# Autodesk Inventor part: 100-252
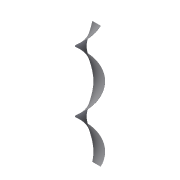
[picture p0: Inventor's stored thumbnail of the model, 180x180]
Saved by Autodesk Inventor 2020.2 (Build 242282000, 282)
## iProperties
Created: 2011-01
Part Number: 100-252
Document SubType Name: Modeling
Designer: F.Stasiak
Density: 1 g/cm^3
Material: Ogólny
Appearance: Domyślna
Company: Fabian Stasiak CAD Consulting
Manager: www.cadconsulting.pl
Author: F.Stasiak
Subject: Zbiór ćwiczeń. Autodesk Inventor 2020. Kurs podstawowy
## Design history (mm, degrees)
sketch "Szkic1"
  geometry: L1 (40, 2.5)-(175, 2.5); L2 (175, 2.5)-(175, -2.5); L3 (175, -2.5)-(40, -2.5); L4 (40, -2.5)-(40, 2.5); 2 further points
  constraints: 8 end point, 2 parallel, 1 horizontal, 1 horizontal alignment, 1 midpoint, 1 perpendicular
  dimensions: "d0" = 135 distance of L2.end L3.end; "d1" = 5 distance of L1.end L2.end; "d2" = 40 distance from line of L4 point (0, 0)
feature "Zwój1" sketch "Szkic1" pitch "d3" = 200; turns "d5" = 2; dims "d4" = 2000, "d6" = 0, angle "d7" = 90 deg, angle "d8" = 90 deg, "d9" = 0, "d10" = 0
node "Bryła1"
